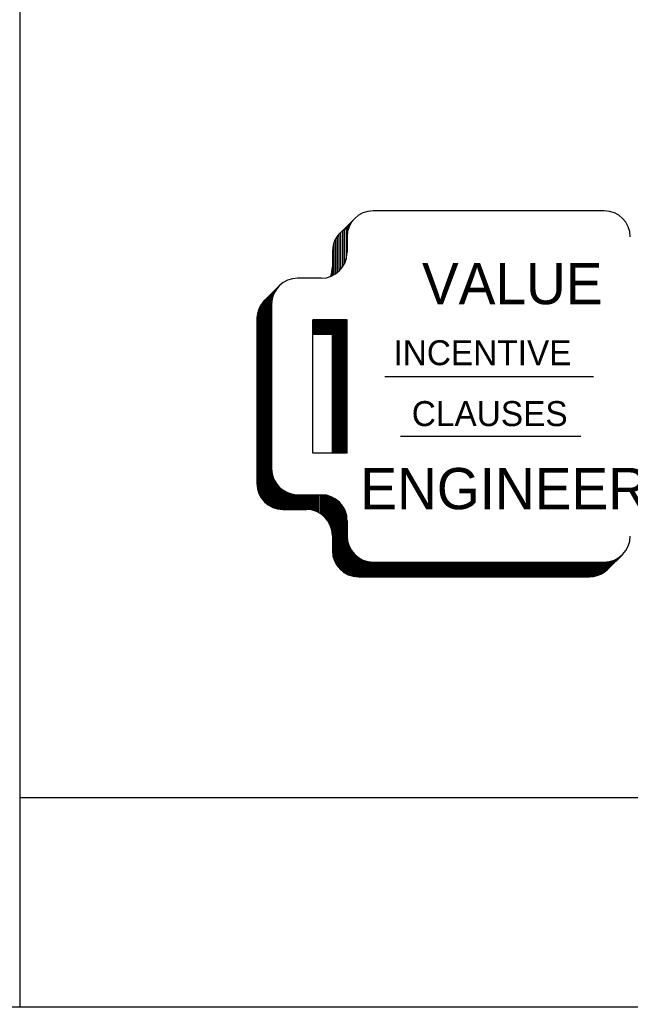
# Model space of a CAD drawing. Extents: x 22369.6 to 22428.3, y 22369.6 to 22415.
# Drawn here: x 22371.62 to 22373.576, y 22369.621 to 22372.784 of the extents above; entities that cross this region are included whole.
import ezdxf

# ---------------------------------------------------------------- set-up
doc = ezdxf.new("R2010")
doc.units = 0
for name, color, linetype in [('Level 1', 7, 'Continuous'), ('Level 10', 7, 'Continuous'), ('Level 2', 7, 'Continuous'), ('Level 7', 7, 'Continuous'), ('Level 9', 7, 'Continuous')]:
    doc.layers.add(name, color=color, linetype=linetype)

msp = doc.modelspace()

# ---------------------------------------------------------------- linework, layer by layer
at = {"layer": 'Level 1'}
msp.add_lwpolyline([(22369.6213, 22414.9653), (22428.2885, 22414.9653), (22428.2885, 22369.6213), (22369.6213, 22369.6213)], close=True, dxfattribs=at)
at = {"layer": 'Level 10'}
msp.add_line((22371.6213, 22369.6213), (22371.6213, 22370.2933), dxfattribs=at)
at = {"layer": 'Level 2'}
for p, q in [((22372.6464, 22372.1007), (22372.6935, 22372.1479)), ((22372.6659, 22372.1202), (22372.6659, 22372.0164)), ((22372.6692, 22372.0889), (22372.6692, 22372.1235)), ((22372.6732, 22372.1144), (22372.6732, 22372.1275)), ((22372.6775, 22372.1252), (22372.6775, 22372.1319)), ((22372.6817, 22372.1327), (22372.6817, 22372.136)), ((22372.6852, 22372.138), (22372.6852, 22372.1395)), ((22372.6374, 22372.0899), (22372.6374, 22371.9742)), ((22372.643, 22372.097), (22372.643, 22371.979)), ((22372.6485, 22372.1029), (22372.6485, 22371.9847)), ((22372.6542, 22372.1085), (22372.6542, 22371.992)), ((22372.6602, 22372.1145), (22372.6602, 22372.002)), ((22372.6265, 22372.0687), (22372.6265, 22371.967)), ((22372.6322, 22372.0815), (22372.6322, 22371.9704)), ((22372.622, 22372.0417), (22372.622, 22371.9647)), ((22372.4044, 22371.8849), (22372.4515, 22371.932)), ((22372.4172, 22371.8977), (22372.4172, 22371.2299)), ((22372.4195, 22371.9), (22372.4195, 22371.2284)), ((22372.4217, 22371.9022), (22372.4217, 22371.227)), ((22372.4239, 22371.9044), (22372.4239, 22371.2259)), ((22372.4254, 22371.9059), (22372.4254, 22371.225)), ((22372.4272, 22371.873), (22372.4272, 22371.9077)), ((22372.429, 22371.8904), (22372.429, 22371.9095)), ((22372.4314, 22371.899), (22372.4314, 22371.9119)), ((22372.4332, 22371.904), (22372.4332, 22371.9137)), ((22372.4349, 22371.9079), (22372.4349, 22371.9154)), ((22372.4364, 22371.911), (22372.4364, 22371.9169)), ((22372.438, 22371.9142), (22372.438, 22371.9185)), ((22372.4397, 22371.9169), (22372.4397, 22371.9202)), ((22372.4414, 22371.9195), (22372.4414, 22371.9219)), ((22372.443, 22371.9219), (22372.443, 22371.9235)), ((22372.3924, 22371.8695), (22372.3924, 22371.2555)), ((22372.395, 22371.8735), (22372.395, 22371.2515)), ((22372.3979, 22371.8774), (22372.3979, 22371.2477)), ((22372.4002, 22371.8802), (22372.4002, 22371.2449)), ((22372.4024, 22371.8827), (22372.4024, 22371.2424)), ((22372.4047, 22371.885), (22372.4047, 22371.24)), ((22372.4075, 22371.888), (22372.4075, 22371.2374)), ((22372.4095, 22371.89), (22372.4095, 22371.2355)), ((22372.4117, 22371.8922), (22372.4117, 22371.2339)), ((22372.4144, 22371.8949), (22372.4144, 22371.2319)), ((22372.3824, 22371.8454), (22372.3824, 22371.2797)), ((22372.3849, 22371.8539), (22372.3849, 22371.2712)), ((22372.3875, 22371.8604), (22372.3875, 22371.2647)), ((22372.3897, 22371.8649), (22372.3897, 22371.2602)), ((22372.38, 22371.8259), (22372.38, 22371.2992)), ((22372.6692, 22371.8209), (22372.5589, 22371.8209)), ((22372.6692, 22371.8187), (22372.5589, 22371.8187)), ((22372.6692, 22371.8162), (22372.5589, 22371.8162)), ((22372.6692, 22371.8137), (22372.5589, 22371.8137)), ((22372.6692, 22371.811), (22372.5589, 22371.811)), ((22372.6692, 22371.8085), (22372.5589, 22371.8085)), ((22372.6692, 22371.806), (22372.5589, 22371.806)), ((22372.6692, 22371.8034), (22372.5589, 22371.8034)), ((22372.6692, 22371.823), (22372.622, 22371.7759)), ((22372.6692, 22371.801), (22372.5589, 22371.801)), ((22372.6692, 22371.7985), (22372.5589, 22371.7985)), ((22372.6692, 22371.796), (22372.5589, 22371.796)), ((22372.6692, 22371.7937), (22372.5589, 22371.7937)), ((22372.6692, 22371.7914), (22372.5589, 22371.7914)), ((22372.6692, 22371.7894), (22372.5589, 22371.7894)), ((22372.6692, 22371.7869), (22372.5589, 22371.7869)), ((22372.6692, 22371.7849), (22372.5589, 22371.7849)), ((22372.6692, 22371.7827), (22372.5589, 22371.7827)), ((22372.6692, 22371.7807), (22372.5589, 22371.7807)), ((22372.6692, 22371.7782), (22372.5589, 22371.7782)), ((22372.622, 22371.7759), (22372.5589, 22371.7759)), ((22372.622, 22371.3964), (22372.622, 22371.7759)), ((22372.6244, 22371.3964), (22372.6244, 22371.7782)), ((22372.6262, 22371.3964), (22372.6262, 22371.7782)), ((22372.6282, 22371.3964), (22372.6282, 22371.7782)), ((22372.6299, 22371.3964), (22372.6299, 22371.7782)), ((22372.6324, 22371.3964), (22372.6324, 22371.7782)), ((22372.6345, 22371.3964), (22372.6345, 22371.7782)), ((22372.6369, 22371.3964), (22372.6369, 22371.7782)), ((22372.6385, 22371.3964), (22372.6385, 22371.7782)), ((22372.6412, 22371.3964), (22372.6412, 22371.7782)), ((22372.6434, 22371.3964), (22372.6434, 22371.7782)), ((22372.6452, 22371.3964), (22372.6452, 22371.7782)), ((22372.6474, 22371.3964), (22372.6474, 22371.7782)), ((22372.6495, 22371.3964), (22372.6495, 22371.7782)), ((22372.652, 22371.3964), (22372.652, 22371.7782)), ((22372.654, 22371.3964), (22372.654, 22371.7782)), ((22372.656, 22371.3964), (22372.656, 22371.7782)), ((22372.6585, 22371.3964), (22372.6585, 22371.7782)), ((22372.661, 22371.3964), (22372.661, 22371.7782)), ((22372.6635, 22371.3964), (22372.6635, 22371.7782)), ((22372.6652, 22371.3964), (22372.6652, 22371.7782)), ((22372.6674, 22371.3964), (22372.6674, 22371.7782)), ((22372.4284, 22371.3325), (22372.4284, 22371.2235)), ((22372.431, 22371.3214), (22372.431, 22371.2224)), ((22372.4335, 22371.3145), (22372.4335, 22371.2214)), ((22372.436, 22371.309), (22372.436, 22371.2205)), ((22372.439, 22371.3035), (22372.439, 22371.2195)), ((22372.4412, 22371.3002), (22372.4412, 22371.2189)), ((22372.4434, 22371.297), (22372.4434, 22371.2184)), ((22372.4462, 22371.2934), (22372.4462, 22371.2177)), ((22372.4485, 22371.2907), (22372.4485, 22371.2172)), ((22372.451, 22371.288), (22372.451, 22371.2169)), ((22372.4535, 22371.2855), (22372.4535, 22371.2164)), ((22372.456, 22371.2834), (22372.456, 22371.2162)), ((22372.4584, 22371.2814), (22372.4584, 22371.216)), ((22372.4612, 22371.2792), (22372.4612, 22371.2159)), ((22372.4637, 22371.2774), (22372.4637, 22371.2159)), ((22372.4662, 22371.2759), (22372.4662, 22371.2159)), ((22372.4687, 22371.2744), (22372.4687, 22371.2159)), ((22372.4717, 22371.2727), (22372.4717, 22371.2159)), ((22372.4739, 22371.2715), (22372.4739, 22371.2159)), ((22372.4752, 22371.2709), (22372.4752, 22371.2159)), ((22372.4774, 22371.2699), (22372.4774, 22371.2159)), ((22372.4795, 22371.269), (22372.4795, 22371.2159)), ((22372.4822, 22371.268), (22372.4822, 22371.2159)), ((22372.4849, 22371.267), (22372.4849, 22371.2159)), ((22372.4874, 22371.2664), (22372.4874, 22371.2159)), ((22372.4907, 22371.2654), (22372.4907, 22371.2159)), ((22372.4937, 22371.2647), (22372.4937, 22371.2159)), ((22372.4962, 22371.2642), (22372.4962, 22371.2159)), ((22372.498, 22371.264), (22372.498, 22371.2159)), ((22372.5005, 22371.2637), (22372.5005, 22371.2159)), ((22372.5027, 22371.2634), (22372.5027, 22371.2159)), ((22372.5045, 22371.2632), (22372.5045, 22371.2159)), ((22372.5069, 22371.263), (22372.5069, 22371.2159)), ((22372.5095, 22371.263), (22372.5095, 22371.2159)), ((22372.512, 22371.263), (22372.512, 22371.2159)), ((22372.5149, 22371.263), (22372.5149, 22371.2159)), ((22372.5177, 22371.263), (22372.5177, 22371.2159)), ((22372.5202, 22371.263), (22372.5202, 22371.2159)), ((22372.5235, 22371.263), (22372.5235, 22371.2159)), ((22372.5264, 22371.263), (22372.5264, 22371.2159)), ((22372.5289, 22371.263), (22372.5289, 22371.2159)), ((22372.5317, 22371.263), (22372.5317, 22371.2159)), ((22372.5349, 22371.263), (22372.5349, 22371.2159)), ((22372.5379, 22371.263), (22372.5379, 22371.2159)), ((22372.541, 22371.263), (22372.541, 22371.2159)), ((22372.5442, 22371.263), (22372.5442, 22371.2159)), ((22372.5479, 22371.263), (22372.5479, 22371.2154)), ((22372.5504, 22371.263), (22372.5504, 22371.215)), ((22372.5525, 22371.263), (22372.5525, 22371.2147)), ((22372.5547, 22371.263), (22372.5547, 22371.2144)), ((22372.5582, 22371.263), (22372.5582, 22371.2135)), ((22372.5619, 22371.263), (22372.5619, 22371.2125)), ((22372.5657, 22371.263), (22372.5657, 22371.2114)), ((22372.5694, 22371.263), (22372.5694, 22371.21)), ((22372.5725, 22371.263), (22372.5725, 22371.2087)), ((22372.5762, 22371.263), (22372.5762, 22371.207)), ((22372.579, 22371.263), (22372.579, 22371.2055)), ((22372.5834, 22371.263), (22372.5834, 22371.2029)), ((22372.5869, 22371.263), (22372.5869, 22371.2005)), ((22372.5887, 22371.263), (22372.5887, 22371.1992)), ((22372.5919, 22371.263), (22372.5919, 22371.1967)), ((22372.5944, 22371.2625), (22372.5944, 22371.1945)), ((22372.597, 22371.2622), (22372.597, 22371.192)), ((22372.5995, 22371.2619), (22372.5995, 22371.1895)), ((22372.6014, 22371.2615), (22372.6014, 22371.1875)), ((22372.6042, 22371.261), (22372.6042, 22371.184)), ((22372.607, 22371.2604), (22372.607, 22371.1802)), ((22372.61, 22371.2595), (22372.61, 22371.1755)), ((22372.6129, 22371.2585), (22372.6129, 22371.1705)), ((22372.6154, 22371.2577), (22372.6154, 22371.1652)), ((22372.618, 22371.2565), (22372.618, 22371.158)), ((22372.6209, 22371.2554), (22372.6209, 22371.1464)), ((22372.623, 22371.2544), (22372.623, 22371.0705)), ((22372.6257, 22371.2529), (22372.6257, 22371.0589)), ((22372.6284, 22371.2514), (22372.6284, 22371.0515)), ((22372.6309, 22371.2499), (22372.6309, 22371.046)), ((22372.6334, 22371.2482), (22372.6334, 22371.0414)), ((22372.6359, 22371.2464), (22372.6359, 22371.0374)), ((22372.6387, 22371.2442), (22372.6387, 22371.0334)), ((22372.6409, 22371.2424), (22372.6409, 22371.0305)), ((22372.6434, 22371.24), (22372.6434, 22371.0277)), ((22372.6455, 22371.2379), (22372.6455, 22371.0254)), ((22372.6482, 22371.235), (22372.6482, 22371.0227)), ((22372.4634, 22371.2159), (22372.5387, 22371.2159)), ((22372.6507, 22371.232), (22372.6507, 22371.0205)), ((22372.6535, 22371.2284), (22372.6535, 22371.018)), ((22372.6562, 22371.2244), (22372.6562, 22371.016)), ((22372.6584, 22371.2209), (22372.6584, 22371.0145)), ((22372.6604, 22371.217), (22372.6604, 22371.0132)), ((22372.662, 22371.2135), (22372.662, 22371.0122)), ((22372.6642, 22371.2082), (22372.6642, 22371.0109)), ((22372.666, 22371.2025), (22372.666, 22371.0099)), ((22372.6675, 22371.1962), (22372.6675, 22371.009)), ((22372.622, 22371.1325), (22372.622, 22371.0834)), ((22372.6694, 22371.1252), (22372.6694, 22371.0082)), ((22372.6717, 22371.1102), (22372.6717, 22371.0072)), ((22372.6739, 22371.103), (22372.6739, 22371.0062)), ((22372.6757, 22371.0982), (22372.6757, 22371.0055)), ((22372.6777, 22371.0939), (22372.6777, 22371.0047)), ((22372.6794, 22371.0907), (22372.6794, 22371.0042)), ((22372.6817, 22371.0867), (22372.6817, 22371.0035)), ((22372.6839, 22371.0834), (22372.6839, 22371.0029)), ((22372.6862, 22371.08), (22372.6862, 22371.0022)), ((22372.6879, 22371.078), (22372.6879, 22371.0019)), ((22372.6902, 22371.0752), (22372.6902, 22371.0014)), ((22372.6915, 22371.0737), (22372.6915, 22371.0012)), ((22372.6934, 22371.0719), (22372.6934, 22371.0009)), ((22372.6954, 22371.0699), (22372.6954, 22371.0007)), ((22372.6969, 22371.0685), (22372.6969, 22371.0005)), ((22372.6979, 22371.0677), (22372.6979, 22371.0004)), ((22372.699, 22371.0667), (22372.699, 22371.0002)), ((22372.7009, 22371.0652), (22372.7009, 22371.0002)), ((22372.7032, 22371.0634), (22372.7032, 22371.0002)), ((22372.7059, 22371.0615), (22372.7059, 22371.0002)), ((22372.7082, 22371.06), (22372.7082, 22371.0002)), ((22372.7109, 22371.0584), (22372.7109, 22371.0002)), ((22372.7134, 22371.057), (22372.7134, 22371.0002)), ((22372.7159, 22371.0557), (22372.7159, 22371.0002)), ((22372.7179, 22371.0547), (22372.7179, 22371.0002)), ((22372.7202, 22371.0537), (22372.7202, 22371.0002)), ((22372.7229, 22371.0527), (22372.7229, 22371.0002)), ((22372.7255, 22371.0517), (22372.7255, 22371.0002)), ((22372.7282, 22371.0509), (22372.7282, 22371.0002)), ((22372.731, 22371.05), (22372.731, 22371.0002)), ((22372.734, 22371.0492), (22372.734, 22371.0002)), ((22372.7364, 22371.0487), (22372.7364, 22371.0002)), ((22372.7394, 22371.0482), (22372.7394, 22371.0002)), ((22372.742, 22371.0479), (22372.742, 22371.0002)), ((22372.7447, 22371.0475), (22372.7447, 22371.0002)), ((22372.7479, 22371.0474), (22372.7479, 22371.0002)), ((22372.7505, 22371.0472), (22372.7505, 22371.0002)), ((22372.7505, 22371.046), (22373.446, 22371.046)), ((22372.7505, 22371.0452), (22373.446, 22371.0452)), ((22372.7505, 22371.0444), (22373.446, 22371.0444)), ((22372.7505, 22371.0432), (22373.446, 22371.0432)), ((22373.446, 22371), (22373.446, 22371.0472)), ((22373.4479, 22371), (22373.4479, 22371.0472)), ((22373.4492, 22371), (22373.4492, 22371.0472)), ((22373.4505, 22371.0002), (22373.4505, 22371.0472)), ((22373.4527, 22371.0004), (22373.4527, 22371.0472)), ((22373.4544, 22371.0005), (22373.4544, 22371.0472)), ((22373.4564, 22371.0007), (22373.4564, 22371.0472)), ((22373.458, 22371.0009), (22373.458, 22371.0472)), ((22373.4599, 22371.0012), (22373.4599, 22371.0472)), ((22373.4614, 22371.0015), (22373.4614, 22371.0472)), ((22373.4634, 22371.0019), (22373.4634, 22371.0472)), ((22373.4652, 22371.0022), (22373.4652, 22371.0472)), ((22373.467, 22371.0027), (22373.467, 22371.0472)), ((22373.4694, 22371.0034), (22373.4694, 22371.0472)), ((22373.4719, 22371.0042), (22373.4719, 22371.0472)), ((22373.4739, 22371.0049), (22373.4739, 22371.0472)), ((22373.4759, 22371.0055), (22373.4759, 22371.0472)), ((22373.478, 22371.0064), (22373.478, 22371.0472)), ((22373.4802, 22371.0074), (22373.4802, 22371.0472)), ((22373.482, 22371.0082), (22373.482, 22371.0472)), ((22373.4845, 22371.0095), (22373.4845, 22371.0472)), ((22373.487, 22371.0109), (22373.487, 22371.0472)), ((22373.4894, 22371.0122), (22373.4894, 22371.0472)), ((22373.4917, 22371.0137), (22373.4917, 22371.0472)), ((22373.494, 22371.0152), (22373.494, 22371.0472)), ((22373.4962, 22371.0169), (22373.4962, 22371.0472)), ((22373.4985, 22371.0187), (22373.4985, 22371.0472)), ((22373.501, 22371.0207), (22373.501, 22371.0475)), ((22373.5034, 22371.0229), (22373.5034, 22371.0479)), ((22373.505, 22371.0244), (22373.5522, 22371.0715)), ((22373.5054, 22371.0247), (22373.5054, 22371.048)), ((22373.5075, 22371.0269), (22373.5075, 22371.0484)), ((22373.5092, 22371.0285), (22373.5092, 22371.0487)), ((22373.5112, 22371.0305), (22373.5112, 22371.0492)), ((22373.5129, 22371.0322), (22373.5129, 22371.0495)), ((22373.5147, 22371.034), (22373.5147, 22371.05)), ((22373.5167, 22371.036), (22373.5167, 22371.0505)), ((22373.518, 22371.0374), (22373.518, 22371.051)), ((22373.5197, 22371.039), (22373.5197, 22371.0515)), ((22373.5212, 22371.0405), (22373.5212, 22371.052)), ((22373.5229, 22371.0422), (22373.5229, 22371.0527)), ((22373.5239, 22371.0432), (22373.5239, 22371.053)), ((22373.5259, 22371.0452), (22373.5259, 22371.0539)), ((22373.5274, 22371.0467), (22373.5274, 22371.0545)), ((22373.529, 22371.0484), (22373.529, 22371.0554)), ((22373.5309, 22371.0502), (22373.5309, 22371.0562)), ((22373.5324, 22371.0517), (22373.5324, 22371.057)), ((22373.5339, 22371.0532), (22373.5339, 22371.0579)), ((22373.5354, 22371.0547), (22373.5354, 22371.0587)), ((22373.537, 22371.0564), (22373.537, 22371.0597)), ((22373.5387, 22371.058), (22373.5387, 22371.0607)), ((22373.5402, 22371.0595), (22373.5402, 22371.0617)), ((22373.5417, 22371.061), (22373.5417, 22371.0627)), ((22373.5432, 22371.0625), (22373.5432, 22371.0639)), ((22372.7505, 22371.0419), (22373.446, 22371.0419)), ((22372.7505, 22371.0404), (22373.446, 22371.0404)), ((22372.7505, 22371.0389), (22373.446, 22371.0389)), ((22372.7505, 22371.0375), (22373.446, 22371.0375)), ((22372.7505, 22371.036), (22373.446, 22371.036)), ((22372.7505, 22371.0345), (22373.446, 22371.0345)), ((22372.7505, 22371.033), (22373.446, 22371.033)), ((22372.7505, 22371.0315), (22373.446, 22371.0315)), ((22372.7505, 22371.03), (22373.446, 22371.03)), ((22372.7505, 22371.0287), (22373.446, 22371.0287)), ((22372.7505, 22371.0272), (22373.446, 22371.0272)), ((22372.7505, 22371.0259), (22373.446, 22371.0259)), ((22372.7505, 22371.0245), (22373.446, 22371.0245)), ((22372.7505, 22371.023), (22373.446, 22371.023)), ((22372.7505, 22371.0215), (22373.446, 22371.0215)), ((22372.7505, 22371.0199), (22373.446, 22371.0199)), ((22372.7505, 22371.0182), (22373.446, 22371.0182)), ((22372.7505, 22371.0165), (22373.446, 22371.0165)), ((22372.7505, 22371.015), (22373.446, 22371.015)), ((22372.7505, 22371.0132), (22373.446, 22371.0132)), ((22372.7505, 22371.0115), (22373.446, 22371.0115)), ((22372.7054, 22371), (22373.446, 22371)), ((22372.7505, 22371.0097), (22373.446, 22371.0097)), ((22372.7505, 22371.0079), (22373.446, 22371.0079)), ((22372.7505, 22371.0059), (22373.446, 22371.0059)), ((22372.7505, 22371.004), (22373.446, 22371.004)), ((22372.7505, 22371.0022), (22373.446, 22371.0022))]:
    msp.add_line(p, q, dxfattribs=at)
for centre, start, end in [((22372.7053, 22372.0416), 111.4079, 180), ((22372.5386, 22371.9925), 338.5921, 0), ((22372.4633, 22371.8258), 111.4079, 180), ((22372.4633, 22371.2991), 180, 270), ((22372.5386, 22371.1325), 0, 90), ((22372.7053, 22371.0833), 180, 270), ((22373.446, 22371.0833), 270, 338.5921)]:
    msp.add_arc(centre, 0.0833, start, end, dxfattribs=at)
at = {"layer": 'Level 7'}
for p, q in [((22373.4932, 22372.1722), (22372.7525, 22372.1722)), ((22372.6692, 22372.0889), (22372.6692, 22372.0397)), ((22372.5859, 22371.9564), (22372.5105, 22371.9564)), ((22372.4272, 22371.873), (22372.4272, 22371.3464)), ((22372.6692, 22371.823), (22372.5589, 22371.823)), ((22372.5589, 22371.3964), (22372.5589, 22371.823)), ((22372.6692, 22371.3964), (22372.6692, 22371.823)), ((22372.79, 22371.6419), (22373.4592, 22371.6419)), ((22372.8404, 22371.4499), (22373.4179, 22371.4499)), ((22372.6692, 22371.3964), (22372.5589, 22371.3964)), ((22372.5105, 22371.263), (22372.5859, 22371.263)), ((22372.6692, 22371.1797), (22372.6692, 22371.1305)), ((22372.7525, 22371.0472), (22373.4932, 22371.0472))]:
    msp.add_line(p, q, dxfattribs=at)
for centre, start, end in [((22372.7525, 22372.0888), 90, 180), ((22373.4931, 22372.0888), 0, 90), ((22372.5858, 22372.0396), 270, 0), ((22372.5105, 22371.873), 90, 180), ((22372.5105, 22371.3463), 180, 270), ((22372.5858, 22371.1796), 0, 90), ((22372.7525, 22371.1305), 180, 270), ((22373.4931, 22371.1305), 270, 0)]:
    msp.add_arc(centre, 0.0833, start, end, dxfattribs=at)
at = {"layer": 'Level 9'}
for q in [(22371.6213, 22414.2933), (22423.9525, 22370.2933)]:
    msp.add_line((22371.6213, 22370.2933), q, dxfattribs=at)

# ---------------------------------------------------------------- texts
at = {"layer": 'Level 2'}
for s, height, p in [('VALUE', 0.13199, (22372.909, 22371.873)), ('INCENTIVE', 0.08, (22372.8177, 22371.6777)), ('CLAUSES', 0.08, (22372.8764, 22371.4827)), ('ENGINEERING', 0.13199, (22372.7114, 22371.2165))]:
    msp.add_text(s, height=height, dxfattribs=at).set_placement(p)

doc.saveas('drawing.dxf')
